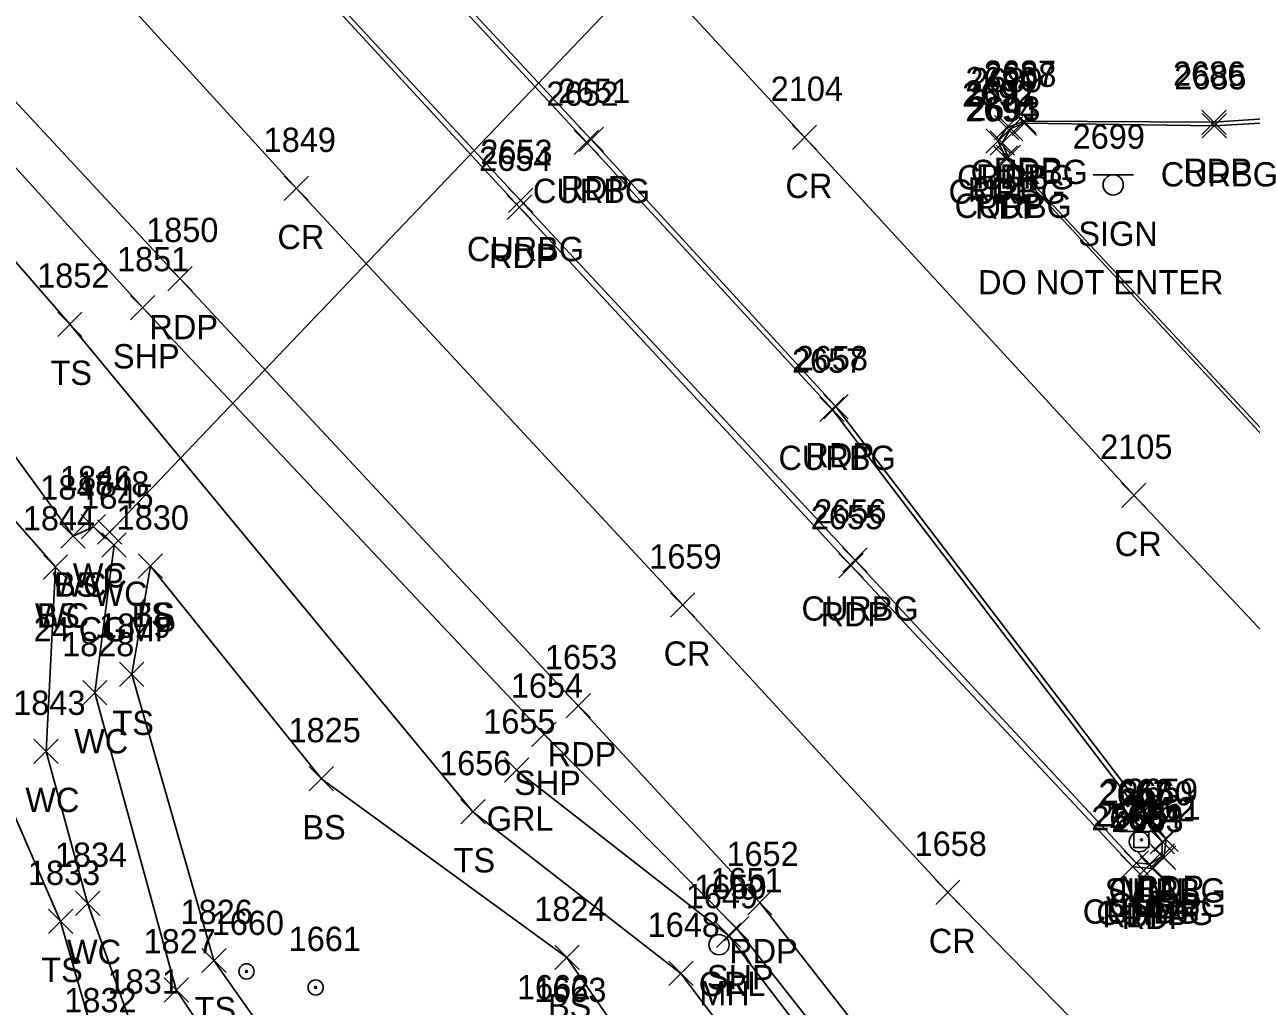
# Model space of a CAD drawing. Extents: x 1623612 to 1625808, y 621345 to 627748.
# Drawn here: x 1624593.7 to 1624694.8, y 626379.2 to 626460 of the extents above; entities that cross this region are included whole.
import ezdxf

# ---------------------------------------------------------------- set-up
doc = ezdxf.new("R2010")
doc.units = 0
for name, color, linetype in [('D_A', 7, 'Continuous'), ('D_C', 7, 'Continuous'), ('D_I', 7, 'Continuous'), ('D_TIC', 7, 'Continuous'), ('DCP', 7, 'Continuous'), ('L_A', 7, 'Continuous'), ('L_I', 7, 'Continuous'), ('L_TIC', 7, 'Continuous'), ('LAWE', 7, 'Continuous'), ('LELB', 7, 'Continuous'), ('P_A', 7, 'Continuous'), ('P_I', 7, 'Continuous'), ('P_TIC', 7, 'Continuous'), ('PET', 7, 'Continuous'), ('PRC', 7, 'Continuous'), ('PSP', 7, 'Continuous'), ('R_A', 7, 'Continuous'), ('R_I', 7, 'Continuous'), ('R_TIC', 7, 'Continuous'), ('RC', 7, 'Continuous'), ('RGR', 7, 'Continuous'), ('S_A', 7, 'Continuous'), ('S_C', 7, 'Continuous'), ('S_I', 7, 'Continuous'), ('SRM', 7, 'Continuous'), ('SSGN', 7, 'Continuous'), ('U_A', 7, 'Continuous'), ('U_I', 7, 'Continuous'), ('UPGW', 7, 'Continuous'), ('UUMH', 7, 'Continuous')]:
    doc.layers.add(name, color=color, linetype=linetype)

msp = doc.modelspace()

# ---------------------------------------------------------------- linework, layer by layer
at = {"layer": 'D_TIC'}
for points in [[(1624599.74, 626417.24), (1624601.74, 626419.24)], [(1624601.74, 626417.24), (1624599.74, 626419.24)]]:
    msp.add_lwpolyline(points, dxfattribs=at)
at = {"layer": 'DCP'}
msp.add_lwpolyline([(1624600.74, 626418.24), (1624712.81, 626535.59)], dxfattribs=at)
at = {"layer": 'L_TIC'}
for points in [[(1624596.45, 626434.36), (1624598.45, 626436.36)], [(1624598.45, 626434.36), (1624596.45, 626436.36)], [(1624598.39, 626417.68), (1624600.39, 626419.68)], [(1624600.39, 626417.68), (1624598.39, 626419.68)], [(1624596.72, 626416.92), (1624598.72, 626418.92)], [(1624598.72, 626416.92), (1624596.72, 626418.92)], [(1624596.72, 626416.92), (1624598.72, 626418.92)], [(1624598.72, 626416.92), (1624596.72, 626418.92)], [(1624600.1, 626416.17), (1624602.1, 626418.17)], [(1624602.1, 626416.17), (1624600.1, 626418.17)], [(1624595.27, 626414.38), (1624597.27, 626416.38)], [(1624597.27, 626414.38), (1624595.27, 626416.38)], [(1624595.27, 626414.38), (1624597.27, 626416.38)], [(1624597.27, 626414.38), (1624595.27, 626416.38)], [(1624603.09, 626414.44), (1624605.09, 626416.44)], [(1624605.09, 626414.44), (1624603.09, 626416.44)], [(1624603.09, 626414.44), (1624605.09, 626416.44)], [(1624605.09, 626414.44), (1624603.09, 626416.44)], [(1624601.55, 626405.54), (1624603.55, 626407.54)], [(1624603.55, 626405.54), (1624601.55, 626407.54)], [(1624598.51, 626404.02), (1624600.51, 626406.02)], [(1624600.51, 626404.02), (1624598.51, 626406.02)], [(1624594.49, 626399.19), (1624596.49, 626401.19)], [(1624596.49, 626399.19), (1624594.49, 626401.19)], [(1624617.17, 626396.94), (1624619.17, 626398.94)], [(1624619.17, 626396.94), (1624617.17, 626398.94)], [(1624629.66, 626394.22), (1624631.66, 626396.22)], [(1624631.66, 626394.22), (1624629.66, 626396.22)], [(1624597.91, 626386.68), (1624599.91, 626388.68)], [(1624599.91, 626386.68), (1624597.91, 626388.68)], [(1624595.69, 626385.19), (1624597.69, 626387.19)], [(1624597.69, 626385.19), (1624595.69, 626387.19)], [(1624637.4, 626382.22), (1624639.4, 626384.22)], [(1624639.4, 626382.22), (1624637.4, 626384.22)], [(1624608.32, 626381.97), (1624610.32, 626383.97)], [(1624610.32, 626381.97), (1624608.32, 626383.97)], [(1624646.79, 626380.91), (1624648.79, 626382.91)], [(1624648.79, 626380.91), (1624646.79, 626382.91)], [(1624605.22, 626379.55), (1624607.22, 626381.55)], [(1624607.22, 626379.55), (1624605.22, 626381.55)]]:
    msp.add_lwpolyline(points, dxfattribs=at)
at = {"layer": 'LAWE'}
for points in [[(1624478.34, 625960.64), (1624502.51, 626006.49), (1624510.02, 626033.48), (1624538.01, 626022.07), (1624539, 626026.11), (1624515.37, 626039.01), (1624525.82, 626080.12), (1624541.49, 626122.12), (1624557.13, 626161.32), (1624574.3, 626199.4), (1624588.96, 626242.23), (1624604.56, 626282.04), (1624612.69, 626318.46), (1624618.16, 626354.23), (1624633.32, 626339.44), (1624651.01, 626315.35), (1624653.64, 626319.94), (1624637.21, 626339.9), (1624620.54, 626359.04), (1624606.22, 626380.55), (1624599.51, 626405.02), (1624601.1, 626417.17), (1624599.39, 626418.68), (1624597.72, 626417.92)], [(1624475.9, 625962), (1624495.4, 626010.74), (1624513.45, 626053.64), (1624523.83, 626080.72), (1624539.75, 626122.53), (1624554.03, 626163.77), (1624569.78, 626201.47), (1624586.16, 626244.06), (1624600.64, 626283.77), (1624605.98, 626319.56), (1624614.72, 626357.4), (1624602.68, 626377.24), (1624598.91, 626387.68), (1624595.49, 626400.19), (1624596.27, 626415.38)]]:
    msp.add_lwpolyline(points, dxfattribs=at)
at = {"layer": 'LELB'}
for points in [[(1624597.72, 626417.92), (1624590.15, 626428.27), (1624581.6, 626439.29), (1624575.06, 626444.11), (1624569.24, 626450.89), (1624572.53, 626454), (1624541.74, 626486.68), (1624523.26, 626507.42), (1624491.29, 626542.02), (1624460.52, 626578.65), (1624432.88, 626609.23), (1624426.51, 626611.96), (1624422.61, 626606.73)], [(1624669.8, 626328.28), (1624669.98, 626343.79), (1624664.44, 626357.31), (1624659.04, 626367.02), (1624647.79, 626381.91), (1624630.66, 626395.22), (1624597.45, 626435.36), (1624575.8, 626460.21), (1624547.36, 626492.23), (1624525.96, 626513.7), (1624497.97, 626546.1), (1624463.72, 626581.44), (1624438.46, 626609.8)], [(1624596.27, 626415.38), (1624586.56, 626426.42), (1624565.06, 626445.8), (1624539.41, 626483.85), (1624522.25, 626503.35), (1624489.26, 626540.68), (1624457.42, 626576.25), (1624422.61, 626606.73)], [(1624405.5, 625728.14), (1624428.24, 625773.19), (1624451.7, 625813.41), (1624479.3, 625869.39), (1624496.23, 625906.08), (1624514.91, 625948.11), (1624536.21, 625990.48), (1624546.45, 626029.66), (1624561.04, 626063.21), (1624576.65, 626110.9), (1624590.48, 626147.32), (1624609.26, 626181.73), (1624628.06, 626219.01), (1624648.51, 626267.43), (1624661.85, 626303.08), (1624661.36, 626343.87), (1624651.86, 626347.04), (1624650.32, 626353.64), (1624652.97, 626362.16), (1624638.4, 626383.22), (1624618.17, 626397.94), (1624604.09, 626415.44)], [(1624658.53, 626316.55), (1624639.28, 626341.89), (1624623.5, 626362.79), (1624609.32, 626382.97), (1624602.55, 626406.54), (1624604.09, 626415.44)], [(1624375.32, 625803.31), (1624399.86, 625843.95), (1624436.39, 625893.65), (1624461.77, 625932.24), (1624474.24, 625964.36), (1624492.43, 626012.44), (1624506.84, 626058.35), (1624517.83, 626084.66), (1624533.25, 626127.2), (1624547.8, 626166.97), (1624564.84, 626204.52), (1624581.23, 626246.76), (1624598.57, 626285.31), (1624600.66, 626320.03), (1624610.19, 626356.83), (1624599.69, 626375.7), (1624596.69, 626386.19), (1624590.38, 626400.67)]]:
    msp.add_lwpolyline(points, dxfattribs=at)
at = {"layer": 'P_TIC'}
for points in [[(1624675.06, 626451.07), (1624677.06, 626453.07)], [(1624677.06, 626451.07), (1624675.06, 626453.07)], [(1624690.7, 626450.99), (1624692.7, 626452.99)], [(1624692.7, 626450.99), (1624690.7, 626452.99)], [(1624673.62, 626450.53), (1624675.62, 626452.53)], [(1624675.62, 626450.53), (1624673.62, 626452.53)], [(1624639.4, 626449.57), (1624641.4, 626451.57)], [(1624641.4, 626449.57), (1624639.4, 626451.57)], [(1624656.97, 626449.75), (1624658.97, 626451.75)], [(1624658.97, 626449.75), (1624656.97, 626451.75)], [(1624672.92, 626449.44), (1624674.92, 626451.44)], [(1624674.92, 626449.44), (1624672.92, 626451.44)], [(1624673.53, 626448.05), (1624675.53, 626450.05)], [(1624675.53, 626448.05), (1624673.53, 626450.05)], [(1624615.12, 626445.54), (1624617.12, 626447.54)], [(1624617.12, 626445.54), (1624615.12, 626447.54)], [(1624633.48, 626443.98), (1624635.48, 626445.98)], [(1624635.48, 626443.98), (1624633.48, 626445.98)], [(1624605.52, 626438.12), (1624607.52, 626440.12)], [(1624607.52, 626438.12), (1624605.52, 626440.12)], [(1624602.46, 626435.72), (1624604.46, 626437.72)], [(1624604.46, 626435.72), (1624602.46, 626437.72)], [(1624659.56, 626427.57), (1624661.56, 626429.57)], [(1624661.56, 626427.57), (1624659.56, 626429.57)], [(1624684.1, 626420.27), (1624686.1, 626422.27)], [(1624686.1, 626420.27), (1624684.1, 626422.27)], [(1624660.8, 626414.48), (1624662.8, 626416.48)], [(1624662.8, 626414.48), (1624660.8, 626416.48)], [(1624646.94, 626411.24), (1624648.94, 626413.24)], [(1624648.94, 626411.24), (1624646.94, 626413.24)], [(1624638.33, 626402.95), (1624640.33, 626404.95)], [(1624640.33, 626402.95), (1624638.33, 626404.95)], [(1624635.52, 626400.6), (1624637.52, 626402.6)], [(1624637.52, 626400.6), (1624635.52, 626402.6)], [(1624686.76, 626391.95), (1624688.76, 626393.95)], [(1624688.76, 626391.95), (1624686.76, 626393.95)], [(1624686.56, 626390.42), (1624688.56, 626392.42)], [(1624688.56, 626390.42), (1624686.56, 626392.42)], [(1624684.01, 626389.69), (1624686.01, 626391.69)], [(1624686.01, 626389.69), (1624684.01, 626391.69)], [(1624684.01, 626389.69), (1624686.01, 626391.69)], [(1624686.01, 626389.69), (1624684.01, 626391.69)], [(1624685.61, 626389.55), (1624687.61, 626391.55)], [(1624687.61, 626389.55), (1624685.61, 626391.55)], [(1624668.78, 626387.58), (1624670.78, 626389.58)], [(1624670.78, 626387.58), (1624668.78, 626389.58)], [(1624653.29, 626386.74), (1624655.29, 626388.74)], [(1624655.29, 626386.74), (1624653.29, 626388.74)], [(1624651.39, 626384.59), (1624653.39, 626386.59)], [(1624653.39, 626384.59), (1624651.39, 626386.59)]]:
    msp.add_lwpolyline(points, dxfattribs=at)
at = {"layer": 'PET'}
for points in [[(1624682.54, 626327.48), (1624678.38, 626346.43), (1624673.34, 626359.16), (1624665.22, 626373.75), (1624654.29, 626387.74), (1624639.33, 626403.95), (1624606.52, 626439.12), (1624581.34, 626466.22), (1624553.07, 626496.91), (1624531.24, 626520.29), (1624503.05, 626550.6), (1624469.83, 626586.28), (1624436.59, 626622.29), (1624410.08, 626650.63), (1624383.72, 626678.98), (1624351.7, 626713.55), (1624321.29, 626745.92), (1624294.74, 626773.91), (1624265.91, 626805.6)], [(1624498.98, 626603.27), (1624497.28, 626604.16), (1624495.57, 626603.5), (1624495.34, 626601.5), (1624514.14, 626578.34), (1624534.8, 626552.7), (1624570.86, 626513.78), (1624602.55, 626479.64), (1624634.48, 626444.98), (1624661.8, 626415.48), (1624685.01, 626390.69)], [(1624498.98, 626603.27), (1624518.99, 626581.66), (1624540.4, 626558.5), (1624576.58, 626519.31), (1624608.93, 626484.4), (1624640.4, 626450.57), (1624660.56, 626428.57), (1624687.76, 626392.95), (1624687.56, 626391.42), (1624686.61, 626390.55), (1624685.01, 626390.69)], [(1624714.78, 626405.78), (1624717.47, 626404.59), (1624725.97, 626424.23), (1624739.05, 626457.71), (1624738.46, 626459.11), (1624736.48, 626459.68), (1624720.92, 626455.4), (1624704.73, 626452.86), (1624691.7, 626451.99), (1624676.06, 626452.07), (1624674.62, 626451.53), (1624673.92, 626450.44), (1624674.53, 626449.05), (1624699.14, 626422.5)]]:
    msp.add_lwpolyline(points, dxfattribs=at)
at = {"layer": 'PRC'}
for points in [[(1624202.38, 626941), (1624231.95, 626909.33), (1624268.3, 626868.91), (1624305.54, 626828.99), (1624337.86, 626793.81), (1624369.19, 626760.84), (1624403.29, 626724.16), (1624436.76, 626689.12), (1624471.08, 626653.03), (1624500.99, 626619.01), (1624533.46, 626585.06), (1624572.18, 626543.82), (1624598.35, 626515.6), (1624627.03, 626484.27), (1624657.97, 626450.75), (1624685.1, 626421.27), (1624710.89, 626393.93)], [(1624691.43, 626366.48), (1624669.78, 626388.58), (1624647.94, 626412.24), (1624616.12, 626446.54), (1624589.59, 626475.6), (1624562.81, 626504.24), (1624540.57, 626528.3), (1624511.37, 626559.76), (1624478.76, 626595.67), (1624444.94, 626631.16), (1624418.89, 626658.65), (1624393.01, 626686.5), (1624360.17, 626722.63), (1624331.53, 626753.24), (1624304.47, 626782.71), (1624275.06, 626813.9), (1624246.4, 626843.61), (1624219.02, 626871.9), (1624198.62, 626894.75), (1624176.28, 626917.84)]]:
    msp.add_lwpolyline(points, dxfattribs=at)
at = {"layer": 'PSP'}
msp.add_lwpolyline([(1624676.55, 626327.48), (1624673.72, 626344.86), (1624670.58, 626356.08), (1624664.11, 626370.71), (1624652.39, 626385.59), (1624636.52, 626401.6), (1624603.46, 626436.72), (1624579, 626463.66), (1624550.01, 626494.21), (1624528.45, 626517.8), (1624500.38, 626548.3), (1624466.85, 626583.85), (1624433.64, 626619.4), (1624408.06, 626646.48), (1624380.64, 626676.32), (1624349.24, 626711.12), (1624317.97, 626743.62), (1624292.14, 626770.88), (1624262.1, 626803.32)], dxfattribs=at)
at = {"layer": 'R_TIC'}
for points in [[(1624675.08, 626450.9), (1624677.08, 626452.9)], [(1624677.08, 626450.9), (1624675.08, 626452.9)], [(1624673.96, 626450.46), (1624675.96, 626452.46)], [(1624675.96, 626450.46), (1624673.96, 626452.46)], [(1624690.74, 626450.7), (1624692.74, 626452.7)], [(1624692.74, 626450.7), (1624690.74, 626452.7)], [(1624639.01, 626449.34), (1624641.01, 626451.34)], [(1624641.01, 626449.34), (1624639.01, 626451.34)], [(1624673.26, 626449.28), (1624675.26, 626451.28)], [(1624675.26, 626449.28), (1624673.26, 626451.28)], [(1624673.76, 626448.11), (1624675.76, 626450.11)], [(1624675.76, 626448.11), (1624673.76, 626450.11)], [(1624633.58, 626444.55), (1624635.58, 626446.55)], [(1624635.58, 626444.55), (1624633.58, 626446.55)], [(1624659.24, 626427.36), (1624661.24, 626429.36)], [(1624661.24, 626427.36), (1624659.24, 626429.36)], [(1624661.13, 626414.95), (1624663.13, 626416.95)], [(1624663.13, 626414.95), (1624661.13, 626416.95)], [(1624633.25, 626397.65), (1624635.25, 626399.65)], [(1624635.25, 626397.65), (1624633.25, 626399.65)], [(1624686.44, 626391.74), (1624688.44, 626393.74)], [(1624688.44, 626391.74), (1624686.44, 626393.74)], [(1624686.44, 626390.57), (1624688.44, 626392.57)], [(1624688.44, 626390.57), (1624686.44, 626392.57)], [(1624684.3, 626390), (1624686.3, 626392)], [(1624686.3, 626390), (1624684.3, 626392)], [(1624684.3, 626390), (1624686.3, 626392)], [(1624686.3, 626390), (1624684.3, 626392)], [(1624685.42, 626389.89), (1624687.42, 626391.89)], [(1624687.42, 626389.89), (1624685.42, 626391.89)], [(1624650.72, 626384.04), (1624652.72, 626386.04)], [(1624652.72, 626384.04), (1624650.72, 626386.04)]]:
    msp.add_lwpolyline(points, dxfattribs=at)
at = {"layer": 'RC'}
for points in [[(1624498.61, 626603.04), (1624497.26, 626603.77), (1624495.94, 626603.19), (1624495.71, 626601.66), (1624514.48, 626578.53), (1624535.04, 626553.01), (1624571.18, 626513.97), (1624602.7, 626479.93), (1624634.58, 626445.55), (1624662.13, 626415.95), (1624685.3, 626391)], [(1624498.61, 626603.04), (1624518.68, 626581.36), (1624539.86, 626558.21), (1624576.35, 626519.14), (1624608.61, 626484.22), (1624640.01, 626450.34), (1624660.24, 626428.36), (1624687.44, 626392.74), (1624687.44, 626391.57), (1624686.42, 626390.89), (1624685.3, 626391)], [(1624715.09, 626406.22), (1624717.37, 626405.41), (1624725.52, 626424.37), (1624738.81, 626457.88), (1624738.51, 626458.9), (1624736.44, 626459.38), (1624721.16, 626455.07), (1624704.93, 626452.47), (1624691.74, 626451.7), (1624676.08, 626451.9), (1624674.96, 626451.46), (1624674.26, 626450.28), (1624674.76, 626449.11), (1624699.26, 626422.83)]]:
    msp.add_lwpolyline(points, dxfattribs=at)
at = {"layer": 'RGR'}
msp.add_lwpolyline([(1624571, 626060.25), (1624575.84, 626063.1), (1624580.53, 626069.08), (1624596.69, 626108.34), (1624613, 626148.3), (1624628.7, 626186.79), (1624643.47, 626223.61), (1624657.22, 626257.17), (1624667.59, 626283.36), (1624674.43, 626306.16), (1624675.65, 626327.64), (1624673.21, 626344.76), (1624670.09, 626355.37), (1624663.71, 626369.31), (1624651.72, 626385.04), (1624634.25, 626398.65)], dxfattribs=at)
at = {"layer": 'SRM'}
msp.add_lwpolyline([(1624685.1, 626393.53), (1624686.35, 626393.53), (1624686.35, 626392.28), (1624685.1, 626392.28)], close=True, dxfattribs=at)
msp.add_circle((1624685.73, 626392.91), 0.0833, dxfattribs=at)
at = {"layer": 'SSGN'}
for p, q in [((1624681.75, 626447.66), (1624685.08, 626447.66)), ((1624683.4, 626446.83), (1624683.4, 626446.83)), ((1624683.91, 626393.58), (1624687.25, 626393.58)), ((1624685.56, 626392.75), (1624685.56, 626392.75))]:
    msp.add_line(p, q, dxfattribs=at)
for centre in [(1624683.4, 626446.83), (1624685.56, 626392.75)]:
    msp.add_circle(centre, 0.833, dxfattribs=at)
at = {"layer": 'UPGW'}
for centre, radius in [((1624612.01, 626382.07), 0.625), ((1624612.01, 626382.07), 0.0833), ((1624617.7, 626380.75), 0.625), ((1624617.7, 626380.75), 0.0833)]:
    msp.add_circle(centre, radius, dxfattribs=at)
at = {"layer": 'UUMH'}
for p, q in [((1624650.93, 626384.27), (1624650.93, 626384.27)), ((1624651.77, 626384.27), (1624651.77, 626384.27))]:
    msp.add_line(p, q, dxfattribs=at)
msp.add_circle((1624650.93, 626384.27), 0.833, dxfattribs=at)

# ---------------------------------------------------------------- texts
at = {"layer": 'D_A'}
msp.add_text('P', height=2, dxfattribs=at).set_placement((1624600.12, 626413.24))
at = {"layer": 'D_C'}
msp.add_text('24 CGMP', height=2, dxfattribs=at).set_placement((1624594.47, 626409.24))
at = {"layer": 'D_I'}
msp.add_text('1848', height=2, dxfattribs=at).set_placement((1624598.05, 626421.24))
at = {"layer": 'L_A'}
for s, p in [('TS', (1624595.86, 626430.36)), ('WC', (1624597.7, 626413.68)), ('WC', (1624596.02, 626412.92)), ('BS', (1624596.16, 626412.92)), ('WC', (1624599.4, 626412.17)), ('TS', (1624602.5, 626410.44)), ('BS', (1624602.54, 626410.44)), ('WC', (1624594.58, 626410.38)), ('BS', (1624594.71, 626410.38)), ('TS', (1624600.96, 626401.54)), ('WC', (1624597.81, 626400.02)), ('WC', (1624593.79, 626395.19)), ('BS', (1624616.61, 626392.94)), ('TS', (1624629.07, 626390.22)), ('WC', (1624597.22, 626382.68)), ('TS', (1624595.1, 626381.19)), ('BS', (1624636.84, 626378.22)), ('TS', (1624607.73, 626377.97))]:
    msp.add_text(s, height=2, dxfattribs=at).set_placement(p)
at = {"layer": 'L_I'}
for s, p in [('1852', (1624594.76, 626438.36)), ('1846', (1624596.64, 626421.68)), ('1847', (1624595.02, 626420.92)), ('1847', (1624595.02, 626420.92)), ('1845', (1624598.4, 626420.17)), ('1844', (1624593.58, 626418.38)), ('1844', (1624593.58, 626418.38)), ('1830', (1624601.31, 626418.44)), ('1830', (1624601.31, 626418.44)), ('1829', (1624599.85, 626409.54)), ('1828', (1624596.81, 626408.02)), ('1843', (1624592.79, 626403.19)), ('1825', (1624615.47, 626400.94)), ('1656', (1624627.87, 626398.22)), ('1834', (1624596.22, 626390.68)), ('1833', (1624594, 626389.19)), ('1824', (1624635.71, 626386.22)), ('1826', (1624606.57, 626385.97)), ('1648', (1624645.05, 626384.91)), ('1827', (1624603.52, 626383.55)), ('1831', (1624600.56, 626380.24)), ('1832', (1624597, 626378.7))]:
    msp.add_text(s, height=2, dxfattribs=at).set_placement(p)
at = {"layer": 'P_A'}
for s, p in [('RDP', (1624673.55, 626447.07)), ('RDP', (1624689.18, 626446.99)), ('RDP', (1624672.11, 626446.53)), ('RDP', (1624637.89, 626445.57)), ('CR', (1624656.4, 626445.75)), ('RDP', (1624671.41, 626445.44)), ('RDP', (1624672.02, 626444.05)), ('CR', (1624614.55, 626441.54)), ('RDP', (1624631.97, 626439.98)), ('RDP', (1624604.01, 626434.12)), ('SHP', (1624601, 626431.72)), ('RDP', (1624658.05, 626423.57)), ('CR', (1624683.53, 626416.27)), ('RDP', (1624659.29, 626410.48)), ('CR', (1624646.37, 626407.24)), ('RDP', (1624636.82, 626398.95)), ('SHP', (1624634.05, 626396.6)), ('RDP', (1624685.24, 626387.95)), ('RDP', (1624685.05, 626386.42)), ('RDP', (1624682.5, 626385.69)), ('RDP', (1624682.5, 626385.69)), ('RDP', (1624684.1, 626385.55)), ('CR', (1624668.21, 626383.58)), ('RDP', (1624651.77, 626382.74)), ('SHP', (1624649.93, 626380.59))]:
    msp.add_text(s, height=2, dxfattribs=at).set_placement(p)
at = {"layer": 'P_I'}
for s, p in [('2687', (1624672.75, 626455.07)), ('2686', (1624688.33, 626454.99)), ('2690', (1624671.23, 626454.53)), ('2651', (1624637.66, 626453.57)), ('2104', (1624655.19, 626453.75)), ('2691', (1624671.18, 626453.44)), ('2694', (1624671.22, 626452.05)), ('1849', (1624613.42, 626449.54)), ('2654', (1624631.17, 626447.98)), ('1850', (1624603.74, 626442.12)), ('1851', (1624601.34, 626439.72)), ('2658', (1624657.25, 626431.57)), ('2105', (1624682.33, 626424.27)), ('2655', (1624658.49, 626418.48)), ('1659', (1624645.19, 626415.24)), ('1653', (1624636.59, 626406.95)), ('1654', (1624633.78, 626404.6)), ('2659', (1624684.44, 626395.95)), ('2662', (1624684.2, 626394.42)), ('2666', (1624681.6, 626393.69)), ('2666', (1624681.6, 626393.69)), ('2663', (1624683.25, 626393.55)), ('1658', (1624667.04, 626391.58)), ('1652', (1624651.54, 626390.74)), ('1651', (1624650.22, 626388.59))]:
    msp.add_text(s, height=2, dxfattribs=at).set_placement(p)
at = {"layer": 'R_A'}
for s, p in [('CURBG', (1624671.66, 626446.9)), ('CURBG', (1624670.54, 626446.46)), ('CURBG', (1624687.32, 626446.7)), ('CURBG', (1624635.6, 626445.34)), ('CURBG', (1624669.84, 626445.28)), ('CURBG', (1624670.34, 626444.11)), ('CURBG', (1624630.16, 626440.55)), ('CURBG', (1624655.83, 626423.36)), ('CURBG', (1624657.72, 626410.95)), ('GRL', (1624631.79, 626393.65)), ('CURBG', (1624683.02, 626387.74)), ('CURBG', (1624683.02, 626386.57)), ('CURBG', (1624680.89, 626386)), ('CURBG', (1624680.89, 626386)), ('CURBG', (1624682.01, 626385.89)), ('GRL', (1624649.26, 626380.04))]:
    msp.add_text(s, height=2, dxfattribs=at).set_placement(p)
at = {"layer": 'R_I'}
for s, p in [('2688', (1624672.77, 626454.9)), ('2689', (1624671.64, 626454.46)), ('2685', (1624688.43, 626454.7)), ('2652', (1624636.71, 626453.34)), ('2692', (1624670.95, 626453.28)), ('2693', (1624671.45, 626452.11)), ('2653', (1624631.27, 626448.55)), ('2657', (1624656.94, 626431.36)), ('2656', (1624658.77, 626418.95)), ('1655', (1624631.51, 626401.65)), ('2660', (1624684, 626395.74)), ('2661', (1624684.65, 626394.57)), ('2665', (1624681.95, 626394)), ('2665', (1624681.95, 626394)), ('2664', (1624683.07, 626393.89)), ('1650', (1624648.89, 626388.04))]:
    msp.add_text(s, height=2, dxfattribs=at).set_placement(p)
at = {"layer": 'S_A'}
for s, p in [('SIGN', (1624680.53, 626441.81)), ('SIGN', (1624682.7, 626387.73)), ('MM', (1624683.92, 626387.91))]:
    msp.add_text(s, height=2, dxfattribs=at).set_placement(p)
at = {"layer": 'S_C'}
msp.add_text('DO NOT ENTER', height=2, dxfattribs=at).set_placement((1624672.27, 626437.81))
at = {"layer": 'S_I'}
for s, p in [('2699', (1624680.06, 626449.81)), ('2667', (1624682.19, 626395.73)), ('2668', (1624682.37, 626395.91))]:
    msp.add_text(s, height=2, dxfattribs=at).set_placement(p)
at = {"layer": 'U_A'}
msp.add_text('MH', height=2, dxfattribs=at).set_placement((1624649.3, 626379.27))
at = {"layer": 'U_I'}
for s, p in [('1649', (1624648.19, 626387.27)), ('1660', (1624609.14, 626385.07)), ('1661', (1624615.48, 626383.75)), ('1662', (1624634.29, 626379.77)), ('1663', (1624635.7, 626379.55))]:
    msp.add_text(s, height=2, dxfattribs=at).set_placement(p)

doc.saveas('drawing.dxf')
